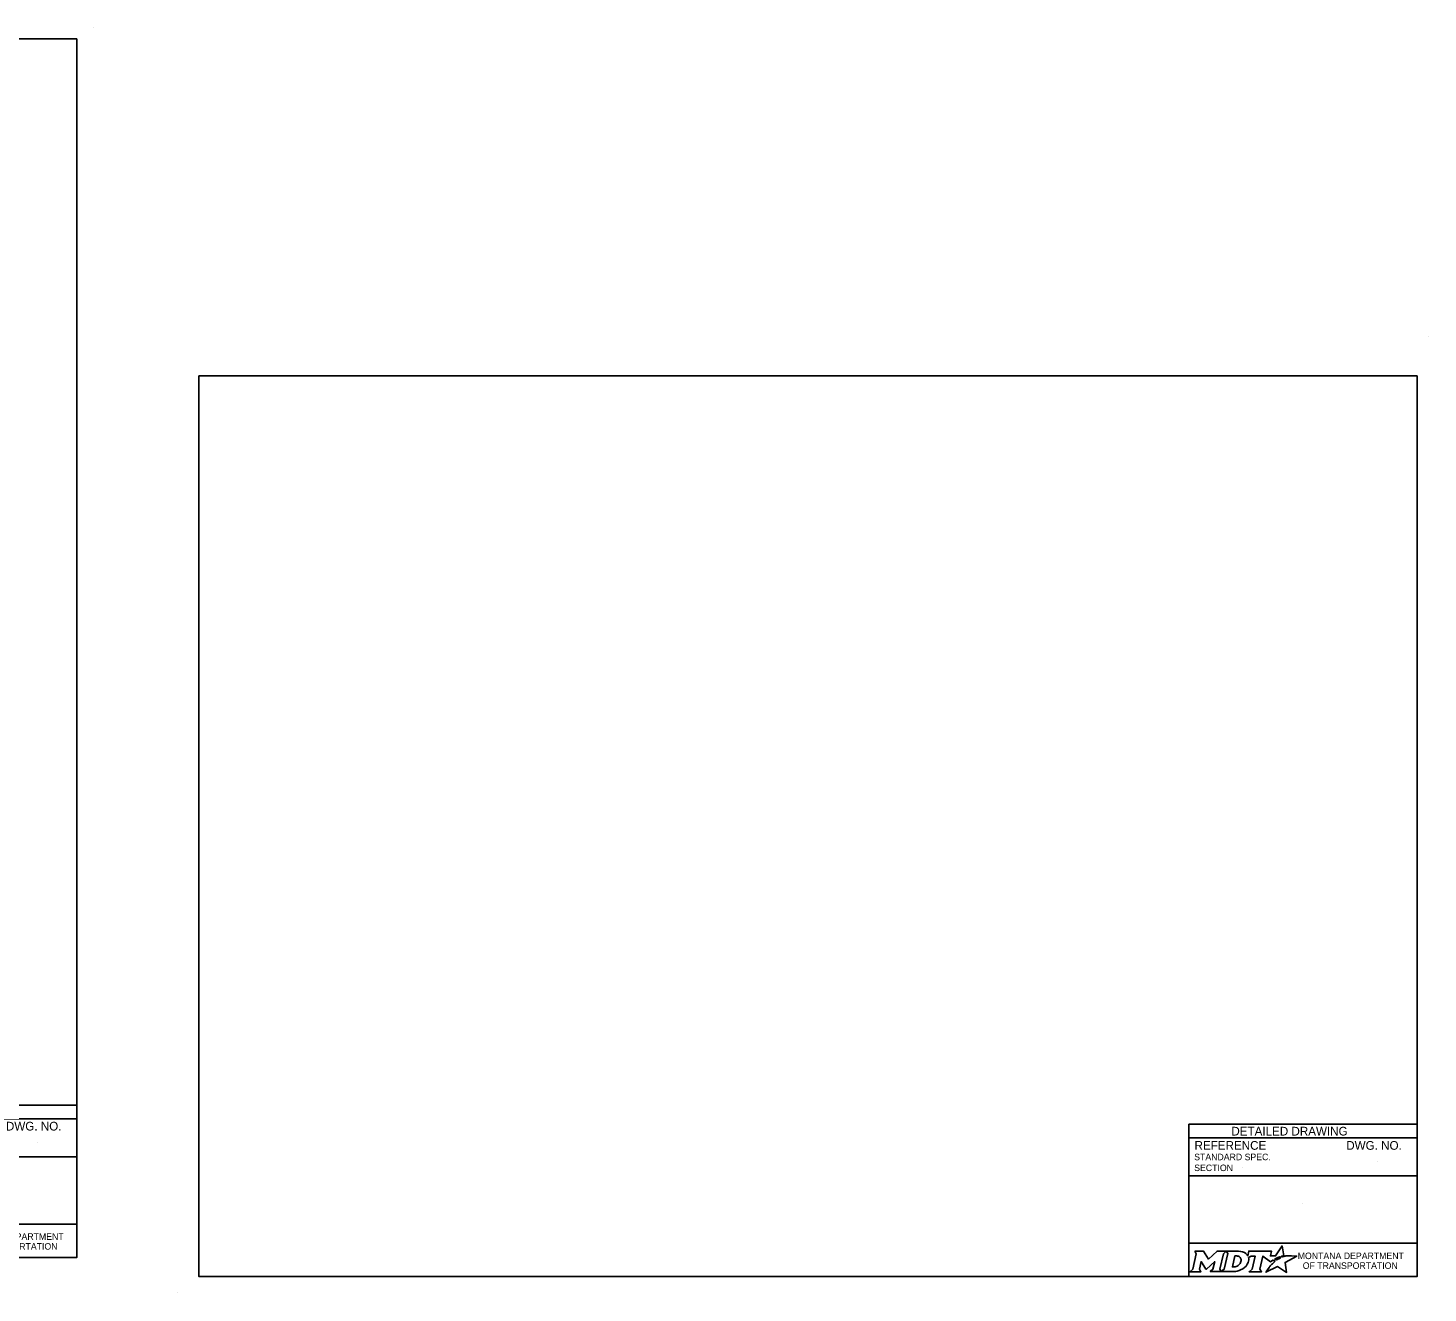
# Model space of a CAD drawing. Extents: x 49991.4 to 50021, y 49987.6 to 50011.4.
# Drawn here: x 50008.17 to 50021.04, y 49999.74 to 50011.36 of the extents above; entities that cross this region are included whole.
import ezdxf

# ---------------------------------------------------------------- set-up
doc = ezdxf.new("R2010")
doc.units = 0
for name, color, linetype in [('Default', 7, 'Continuous'), ('Level 1', 7, 'Continuous'), ('Level 2', 7, 'Continuous'), ('Level 4', 7, 'Continuous')]:
    doc.layers.add(name, color=color, linetype=linetype)

msp = doc.modelspace()

# ---------------------------------------------------------------- linework, layer by layer
at = {"layer": 'Default'}
for points in [[(50018.893, 50000.121), (50018.907, 50000.097), (50018.874, 49999.954), (50018.848, 49999.931), (50018.95, 49999.931), (50018.936, 49999.954), (50018.952, 50000.024), (50018.996, 49999.955), (50019.002, 49999.955), (50019.077, 50000.025), (50019.06, 49999.954), (50019.035, 49999.932), (50019.137, 49999.932), (50019.123, 49999.955), (50019.156, 50000.097)], [(50019.156, 50000.097), (50019.182, 50000.121), (50019.099, 50000.121), (50019.02, 50000.048), (50018.975, 50000.12), (50018.893, 50000.121)], [(50019.295, 50000.121), (50019.182, 50000.121), (50019.196, 50000.098), (50019.163, 49999.954), (50019.137, 49999.932), (50019.248, 49999.932)], [(50019.319, 50000.034), (50019.318, 50000.026), (50019.315, 50000.017), (50019.311, 50000.008), (50019.305, 50000.001), (50019.299, 49999.994), (50019.291, 49999.988), (50019.282, 49999.983), (50019.273, 49999.979), (50019.264, 49999.977), (50019.255, 49999.976), (50019.239, 49999.976), (50019.263, 50000.076), (50019.279, 50000.076), (50019.286, 50000.075), (50019.294, 50000.073), (50019.301, 50000.07), (50019.307, 50000.066), (50019.311, 50000.061), (50019.315, 50000.055), (50019.318, 50000.049), (50019.319, 50000.042), (50019.32, 50000.038), (50019.319, 50000.034)], [(50019.7, 50000.068), (50019.69, 50000.074), (50019.702, 50000.076), (50019.713, 50000.078), (50019.696, 50000.168), (50019.636, 50000.077), (50019.589, 50000.076), (50019.599, 50000.12), (50019.39, 50000.121), (50019.38, 50000.078), (50019.374, 50000.086)], [(50019.387, 50000.062), (50019.411, 50000.075), (50019.448, 50000.075), (50019.42, 49999.954), (50019.392, 49999.931), (50019.508, 49999.931), (50019.491, 49999.954), (50019.52, 50000.075), (50019.591, 50000.023), (50019.612, 50000.038), (50019.632, 50000.027)], [(50019.576, 49999.971), (50019.561, 49999.947), (50019.556, 49999.939), (50019.55, 49999.931), (50019.548, 49999.926), (50019.653, 49999.979), (50019.737, 49999.924), (50019.724, 50000.017), (50019.831, 50000.075), (50019.782, 50000.076), (50019.751, 50000.077), (50019.731, 50000.077), (50019.724, 50000.075), (50019.719, 50000.074), (50019.711, 50000.072), (50019.7, 50000.068)], [(50019.65, 50000.04), (50019.648, 50000.039), (50019.629, 50000.048), (50019.639, 50000.054), (50019.644, 50000.056), (50019.652, 50000.06), (50019.658, 50000.063), (50019.666, 50000.066), (50019.673, 50000.068), (50019.685, 50000.061), (50019.681, 50000.059), (50019.676, 50000.056), (50019.672, 50000.054), (50019.667, 50000.051), (50019.665, 50000.05), (50019.662, 50000.049), (50019.66, 50000.047), (50019.658, 50000.046), (50019.655, 50000.044), (50019.652, 50000.042), (50019.65, 50000.04)], [(50019.293, 49999.939), (50019.302, 49999.942), (50019.315, 49999.947), (50019.335, 49999.958)], [(50019.59, 49999.987), (50019.59, 49999.987)]]:
    msp.add_lwpolyline(points, dxfattribs=at)
for centre, radius, start, end in [((50019.319, 50000.042), 0.0709, 339.5329, 15.8582), ((50019.274, 50000.059), 0.118, 300.9103, 339.1383)]:
    msp.add_arc(centre, radius, start, end, dxfattribs=at)
for centre, major_axis, ratio, start_param, end_param in [((50019.293, 50000.073), (0.0834, -0.0037), 0.568097, 0.61298, 1.570796), ((50019.349, 50000.081), (0.0361, -0.0295), 0.469099, 1.225588, 1.570796), ((50019.248, 50000.08), (0, 0.148), 0.987302, 3.139398, 3.456847), ((50019.583, 49999.979), (-0.00694, -0.00806), 0.008222, 0, 3.137361), ((50019.6, 49999.997), (-0.0098, -0.0102), 0.016458, 3.141593, 6.279097), ((50019.621, 50000.017), (-0.0112, -0.0097), 0.021651, 3.157348, 6.283185)]:
    msp.add_ellipse(centre, major_axis=major_axis, ratio=ratio, start_param=start_param, end_param=end_param, dxfattribs=at)
at = {"layer": 'Level 1'}
for p, q in [((50008.765, 50011.363), (50008.765, 50011.363)), ((50021.038, 50008.524), (50021.038, 50008.524)), ((50009.537, 49999.736), (50009.537, 49999.736))]:
    msp.add_line(p, q, dxfattribs=at)
for points in [[(50008.615, 50011.263), (50000.336, 50011.263), (50000.336, 50000.062), (50008.615, 50000.062)], [(50020.938, 50008.165), (50009.737, 50008.165), (50009.737, 49999.886), (50020.938, 49999.886)]]:
    msp.add_lwpolyline(points, close=True, dxfattribs=at)
at = {"layer": 'Level 2'}
for p, q in [((50008.615, 50001.462), (50006.515, 50001.462)), ((50008.615, 50001.337), (50006.515, 50001.337)), ((50008.251, 50001.122), (50008.251, 50001.122)), ((50008.615, 50000.987), (50006.515, 50000.987)), ((50008.615, 50000.369), (50006.515, 50000.369))]:
    msp.add_line(p, q, dxfattribs=at)
at = {"layer": 'Level 4'}
for p, q in [((50020.938, 50001.286), (50018.838, 50001.286)), ((50018.838, 50001.286), (50018.838, 49999.886)), ((50020.938, 50001.161), (50018.838, 50001.161)), ((50019.332, 50000.886), (50019.332, 50000.886)), ((50020.574, 50000.946), (50020.574, 50000.946)), ((50020.938, 50000.811), (50018.838, 50000.811)), ((50019.888, 50000.562), (50019.888, 50000.562)), ((50020.938, 50000.193), (50018.838, 50000.193))]:
    msp.add_line(p, q, dxfattribs=at)

# ---------------------------------------------------------------- texts
at = {"layer": 'Default'}
for s, p in [('MONTANA DEPARTMENT', (50019.84, 50000.047)), ('OF TRANSPORTATION', (50019.886, 49999.957))]:
    msp.add_text(s, height=0.06, rotation=360, dxfattribs=at).set_placement(p)
at = {"layer": 'Level 2'}
msp.add_text('DWG. NO.', height=0.08, dxfattribs=at).set_placement((50007.962, 50001.229))
for s, p in [('MONTANA DEPARTMENT', (50007.517, 50000.224)), ('OF TRANSPORTATION', (50007.563, 50000.134))]:
    msp.add_text(s, height=0.06, rotation=360, dxfattribs=at).set_placement(p)
at = {"layer": 'Level 4'}
for s, height, p in [('DETAILED DRAWING', 0.0799, (50019.23, 50001.183)), ('REFERENCE', 0.08, (50018.891, 50001.052)), ('DWG. NO.', 0.08, (50020.286, 50001.052)), ('STANDARD SPEC.', 0.06, (50018.888, 50000.956)), ('SECTION', 0.06, (50018.888, 50000.856))]:
    msp.add_text(s, height=height, dxfattribs=at).set_placement(p)

doc.saveas('drawing.dxf')
